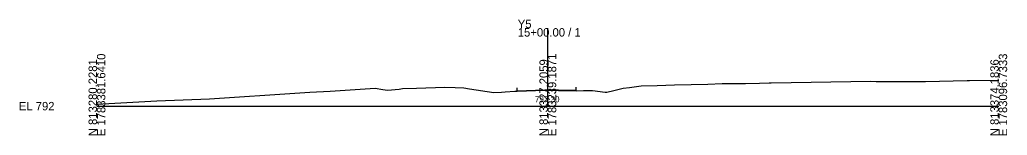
# Model space of a CAD drawing. Extents: x -26 to 1603, y -10 to 6526.
# Drawn here: x 1274.3 to 1602.8, y 1990.3 to 2028.8 of the extents above; entities that cross this region are included whole.
import ezdxf

# ---------------------------------------------------------------- set-up
doc = ezdxf.new("R2010")
doc.units = 0
for name, color, linetype in [('Exist Cross Section Cell', 7, 'Continuous'), ('Exist XS Center Line Elevation Label', 7, 'Continuous'), ('Exist XS Ground Line', 7, 'Continuous'), ('Prop XS EOT Tick Mark', 7, 'Continuous'), ('Prop XS Finish Grade Pavement', 7, 'Continuous')]:
    doc.layers.add(name, color=color, linetype=linetype)

msp = doc.modelspace()

# ---------------------------------------------------------------- linework, layer by layer
at = {"layer": 'Exist Cross Section Cell'}
for p, q in [((1450, 2000), (1450, 2025.95)), ((1300, 2000), (1450, 2000)), ((1450, 2000), (1600, 2000))]:
    msp.add_line(p, q, dxfattribs=at)
at = {"layer": 'Exist XS Ground Line'}
for p, q in [((1492.09, 2007.08), (1503.22, 2007.35)), ((1503.22, 2007.35), (1508, 2007.5)), ((1508, 2007.5), (1509.53, 2007.51)), ((1509.53, 2007.51), (1515.71, 2007.58)), ((1515.71, 2007.58), (1520.45, 2007.64)), ((1520.45, 2007.64), (1523.59, 2007.78)), ((1523.59, 2007.78), (1523.92, 2007.79)), ((1523.92, 2007.79), (1524.31, 2007.79)), ((1524.31, 2007.79), (1557.41, 2008.26)), ((1557.41, 2008.26), (1559.27, 2008.18)), ((1559.27, 2008.18), (1562.42, 2008.2)), ((1562.42, 2008.2), (1564.79, 2008.18)), ((1564.79, 2008.18), (1573.51, 2008.23)), ((1573.51, 2008.23), (1575.66, 2008.25)), ((1575.66, 2008.25), (1589.51, 2008.49)), ((1589.51, 2008.49), (1589.81, 2008.49)), ((1589.81, 2008.49), (1590.23, 2008.5)), ((1590.23, 2008.5), (1600, 2008.65)), ((1337.47, 2002.43), (1367.45, 2004.41)), ((1367.45, 2004.41), (1370.79, 2004.6)), ((1370.79, 2004.6), (1377.58, 2004.95)), ((1377.58, 2004.95), (1392.54, 2005.96)), ((1392.54, 2005.96), (1395.15, 2005.5)), ((1395.15, 2005.5), (1396.62, 2005.29)), ((1396.62, 2005.29), (1400.53, 2005.65)), ((1400.53, 2005.65), (1401.62, 2005.86)), ((1401.62, 2005.86), (1406.35, 2005.97)), ((1406.35, 2005.97), (1415.78, 2006.27)), ((1415.78, 2006.27), (1419.19, 2006.18)), ((1419.19, 2006.18), (1422.04, 2006.11)), ((1422.04, 2006.11), (1423.91, 2005.81)), ((1423.91, 2005.81), (1432.06, 2004.53)), ((1432.06, 2004.53), (1434.62, 2004.62)), ((1434.62, 2004.62), (1435.84, 2004.74)), ((1435.84, 2004.74), (1439.07, 2004.96)), ((1439.07, 2004.96), (1439.78, 2005)), ((1439.78, 2005), (1449.04, 2005.29)), ((1449.04, 2005.29), (1449.66, 2005.3)), ((1449.66, 2005.3), (1450, 2005.3)), ((1450, 2005.3), (1453.56, 2005.24)), ((1453.56, 2005.24), (1459.41, 2005.14)), ((1459.41, 2005.14), (1461.88, 2005.16)), ((1461.88, 2005.16), (1464.81, 2005.21)), ((1464.81, 2005.21), (1469.12, 2004.7)), ((1469.12, 2004.7), (1469.64, 2004.65)), ((1469.64, 2004.65), (1470.52, 2004.86)), ((1470.52, 2004.86), (1471.05, 2004.99)), ((1471.05, 2004.99), (1471.55, 2005.11)), ((1471.55, 2005.11), (1475.07, 2005.93)), ((1475.07, 2005.93), (1477.22, 2006.19)), ((1477.22, 2006.19), (1481, 2006.78)), ((1481, 2006.78), (1486.32, 2006.91)), ((1486.32, 2006.91), (1492.09, 2007.08)), ((1300, 2000.67), (1319.9, 2001.75)), ((1319.9, 2001.75), (1337.47, 2002.43))]:
    msp.add_line(p, q, dxfattribs=at)
at = {"layer": 'Prop XS EOT Tick Mark'}
for p, q in [((1439.78, 2005.12), (1439.78, 2006.12)), ((1459.41, 2005.27), (1459.41, 2006.27))]:
    msp.add_line(p, q, dxfattribs=at)
at = {"layer": 'Prop XS Finish Grade Pavement'}
for p, q in [((1439.78, 2005.12), (1449.04, 2005.41)), ((1449.04, 2005.41), (1449.66, 2005.43)), ((1449.66, 2005.43), (1450, 2005.42)), ((1450, 2005.42), (1453.56, 2005.37)), ((1453.56, 2005.37), (1459.41, 2005.27))]:
    msp.add_line(p, q, dxfattribs=at)

# ---------------------------------------------------------------- texts
at = {"layer": 'Exist Cross Section Cell'}
for s, p in [('Y5', (1440, 2025.95)), ('15+00.00 / 1', (1440, 2023.15)), ('EL 792', (1274, 1998.6))]:
    msp.add_text(s, height=2.8, dxfattribs=at).set_placement(p)
for s, p in [('E 1783381.6410', (1302.8, 1990)), ('E 1783239.1871', (1452.8, 1990)), ('E 1783096.7333', (1602.8, 1990)), ('N 813280.2281', (1300, 1990)), ('N 813327.2059', (1450, 1990)), ('N 813374.1836', (1600, 1990))]:
    msp.add_text(s, height=2.8, rotation=90, dxfattribs=at).set_placement(p)
at = {"layer": 'Exist XS Center Line Elevation Label'}
msp.add_text('797.30', height=2, dxfattribs=at).set_placement((1445.71, 2001.3))

doc.saveas('drawing.dxf')
